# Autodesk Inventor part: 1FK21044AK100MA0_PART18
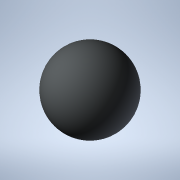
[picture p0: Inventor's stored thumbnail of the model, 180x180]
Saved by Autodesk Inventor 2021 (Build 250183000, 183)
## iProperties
Created: 2025-04
Part Number: 1FK21044AK100MA0_PART18
Material: Generic
Catalog Web Link: www.3dfindit.com
Description: -Servo synchronous motor
Document SubType Name: Modeling
Designer: psAdmin
Mass: 0.137258 g
Surface Area: 1.2868 cm^2
Volume: 0.137258 cm^3
Density: 1 g/cm^3
Appearance: PSOLRGB-212-217-219
Category: PARTsolutions
Title: 1FK21044AK100MA0_PART18
Author: Cadenas PARTsolutions
Comments: Servo synchronous motor
Sending System: PARTsolutions
Preprocessor: ST-DEVELOPER v19.3
PSOL_IDENT_0: {$CADENAS_DATA/23d-libs/siemens_ag/_cat_/5e/d8/1fk21044ak100ma0.prj},216 {VTYP=3D},{NB=1FK21044AK100
PSOL_IDENT_1: MA0_PART18},{LINA=1FK21044AK100MA0_PART18},{NN=1FK21044AK100MA0_PART18},{NOPRJ=TRUE},{DATE=19.08.202
PSOL_IDENT_2: 5 14:00:41},{GEOMDATE=30.07.2025 02:00:53},{VERSION=},{LINEID=10},{WBVAR=},{WBNUMERIC=}  {NB=1FK2104
PSOL_IDENT_3: 4AK100MA0_PART18},{LINA=1FK21044AK100MA0_PART18},{KT=DUMMY},{PREVIEW=../../../_pool_/cb/72/p_d211_xx
PSOL_IDENT_4: _00434j.png},{DESCSHORT=SIMOTICS S-1FK2 HD, SINAMICS S210 3AC 400V-480V, 0.95 Nm, 6000 rpm},{DESCLON
PSOL_IDENT_5: G=SIMOTICS S-1FK2 HD servo motor M0=1.27 Nm; PN = 0.6 kW at nN=6000 rpm (380-480 V); PN = 0.4 kW at
PSOL_IDENT_6: nN=3000 rpm (200-240 V); with holding brake; degree of protection IP64; cylindrical shaft D19x40mm;
PSOL_IDENT_7: absolute encoder 22-bit + 12-bit multiturn (encoder AM22DQC); with OCC interface; plug size M17, rot
PSOL_IDENT_8: atable; SIMOTICS S-1FK2 servomotorfor a wide range of uses in industrial environments. SIMOTICS S‑1F
PSOL_IDENT_9: K2 servomotors are compact synchronous motors with a high dynamic performance that set themselves ap
PSOL_IDENT_10: art as a result of their high power density, degree of protection and overload capability. The motor
PSOL_IDENT_11: s are available in two variants: as High Dynamic variant (highest dynamic performance as a result of
PSOL_IDENT_12: the low intrinsic moment of inertia for applications demanding a high dynamic performance with low
PSOL_IDENT_13: moved masses) - and as Compact variant (precise and stable closed-loop control for medium up to larg
PSOL_IDENT_14: e moved masses as a result of a medium intrinsic moment of inertia). SIMOTICSS‑1FK2 servomotors full
PSOL_IDENT_15: y exploit their strengths in a system with the SINAMICSS210 frequency converter and simple connectio
PSOL_IDENT_16: n using the one cable connection (OCC). Advantages include the short control and positioning times,
PSOL_IDENT_17: fast and precise correction of disturbing quantities as well as stable control with a high dynamic p
PSOL_IDENT_18: erformance. The servo motors can be configured to address a wide range of requirements. For example
PSOL_IDENT_19: with and without holding brake, IP64 or IP65 degree of protection, singleturn or multiturn absolute
PSOL_IDENT_20: encoders - to name just a few. Further, the servomotors are available in different shaft heights ext
PSOL_IDENT_21: ending from 20 to 100. A shaft sealing ring is available to achieve an IP65 degree of protection and
PSOL_IDENT_22: for subsequent mounting at the motor or as spare part. SIMOTICS - the optimum motor for each and ev
PSOL_IDENT_23: ery motion control application.},{INTNO=804766910005},{SUPPLIERALTNO=1FK2104-4AK10-0MA0},{MANUID=1FK
PSOL_IDENT_24: 21044AK100MA0},{MANUNAME=Siemens},{MANUTYPEDESC=Synchronous motor 1FK2-HD 1,27 Nm},{AAU732=SIMOTICS}
PSOL_IDENT_25: ,{AAO057=S-1FK2},{AAU734=SIMOTICS S-1FK2 HD servo motor M0=1.27 Nm; PN = 0.6 kW at nN=6000 rpm (380-
PSOL_IDENT_26: 480 V); PN = 0.4 kW at nN=3000 rpm (200-240 V); with holding brake; degree of protection IP64; cylin
PSOL_IDENT_27: drical shaft D19x40mm; absolute encoder 22-bit + 12-bit multiturn (encoder AM22DQC); with OCC interf
PSOL_IDENT_28: ace; plug size M17, rotatable;},{AAW338=Synchronous motor 1FK2-HD 1,27 Nm},{AAO742=SIMOTICS},{AAO663=
PSOL_IDENT_29: 4042948691076},{NOCUPEROU=1},{PRICEQUANTITY=1},{QUANTITYMIN=1},{QUANTITYINT=1},{CTN=85015100},{COO=D
PSOL_IDENT_30: E},{AAO676=1FK2104-4AK10-0MA0},{AAO677=Siemens AG},{ORDERUNIT=C62},{CONTENTUNIT=C62}
NB: 1FK21044AK100MA0_PART18
NT: Servo synchronous motor
NBSYN: $MANUID._PART18
LINA: 1FK21044AK100MA0_PART18
CATALOG: SIEMENS
PREVIEW: ../../../_pool_/cb/72/p_d211_xx_00434j.png
DESCSHORT: SIMOTICS S-1FK2 HD, SINAMICS S210 3AC 400V-480V, 0.95 Nm, 6000 rpm
DESCLONG: SIMOTICS S-1FK2 HD servo motor M0=1.27 Nm; PN = 0.6 kW at nN=6000 rpm (380-480 V); PN = 0.4 kW at nN=3000 rpm (200-240 V); with holding brake; degree of protect
INTNO: 804766910005
SUPPLIERALTNO: 1FK2104-4AK10-0MA0
MANUID: 1FK21044AK100MA0
MANUNAME: Siemens
MANUTYPEDESC: Synchronous motor 1FK2-HD 1,27 Nm
AAU732: SIMOTICS
AAO057: S-1FK2
AAU734: SIMOTICS S-1FK2 HD servo motor M0=1.27 Nm; PN = 0.6 kW at nN=6000 rpm (380-480 V); PN = 0.4 kW at nN=3000 rpm (200-240 V); with holding brake; degree of protect
AAW338: Synchronous motor 1FK2-HD 1,27 Nm
AAO742: SIMOTICS
AAO663: 4042948691076.0
NOCUPEROU: 1
PRICEQUANTITY: 1
QUANTITYMIN: 1
QUANTITYINT: 1
CTN: 85015100
COO: DE
ARTICLENO: 1FK21044AK100MA0_PART18
BOMINFO: 1FK21044AK100MA0_PART18
CREATOR: CADENAS GmbH
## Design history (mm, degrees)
feature "2025_04_17_15_35_41_0968"
body "Solid1"
